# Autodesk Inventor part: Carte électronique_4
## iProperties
Created: 2010-07
Part Number: Carte électronique_4
Document SubType Name: Modeling
Designer: eric
Density: 1 g/cm^3
Author: eric
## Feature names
1. Base1
